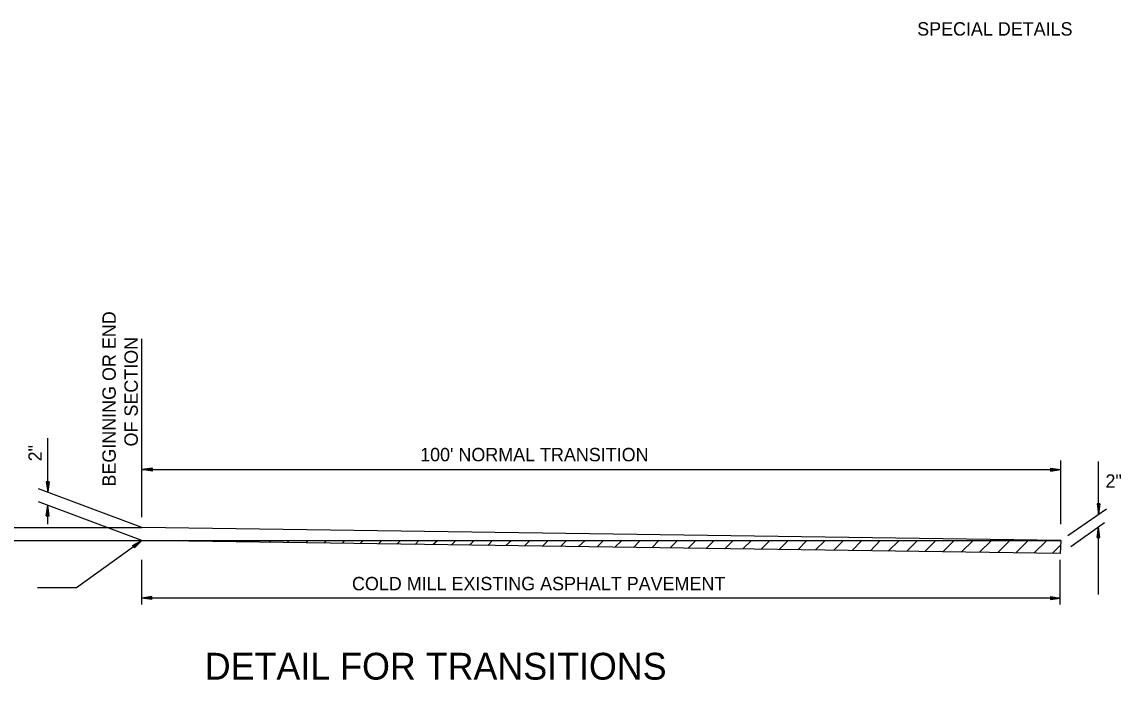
# Model space of a CAD drawing. Extents: x 1955771 to 1955918, y 566326 to 566544.
# Drawn here: x 1955863.97 to 1955913.2, y 566514.53 to 566543.99 of the extents above; entities that cross this region are included whole.
import ezdxf

# ---------------------------------------------------------------- set-up
doc = ezdxf.new("R2010")
doc.units = 0
doc.layers.add('Default', color=7, linetype='Continuous')
doc.layers.add('STAMP', color=7, linetype='Continuous')

msp = doc.modelspace()

# ---------------------------------------------------------------- linework, layer by layer
at = {"layer": 'Default'}
for p, q in [((1955869.343, 566521.819), (1955869.343, 566529.806)), ((1955865.124, 566522.953), (1955865.124, 566525.353)), ((1955910.499, 566521.51), (1955910.499, 566524.352)), ((1955912.186, 566521.953), (1955912.186, 566524.307)), ((1955869.81, 566524.019), (1955869.343, 566523.953)), ((1955869.343, 566523.953), (1955910.499, 566523.953)), ((1955869.81, 566523.886), (1955869.343, 566523.953)), ((1955869.81, 566523.997), (1955869.411, 566523.953)), ((1955869.81, 566523.886), (1955869.411, 566523.953)), ((1955869.81, 566523.997), (1955869.5, 566523.953)), ((1955869.81, 566523.908), (1955869.5, 566523.953)), ((1955869.81, 566523.975), (1955869.589, 566523.953)), ((1955869.81, 566523.908), (1955869.589, 566523.953)), ((1955869.81, 566523.975), (1955869.655, 566523.953)), ((1955869.81, 566523.931), (1955869.655, 566523.953)), ((1955869.81, 566523.953), (1955869.744, 566523.953)), ((1955869.81, 566523.931), (1955869.744, 566523.953)), ((1955869.81, 566523.886), (1955869.81, 566524.019)), ((1955910.032, 566524.019), (1955910.499, 566523.953)), ((1955910.032, 566524.019), (1955910.032, 566523.886)), ((1955910.032, 566523.997), (1955910.344, 566523.953)), ((1955910.032, 566523.997), (1955910.409, 566523.953)), ((1955910.032, 566523.975), (1955910.187, 566523.953)), ((1955910.032, 566523.975), (1955910.255, 566523.953)), ((1955910.032, 566523.886), (1955910.499, 566523.953)), ((1955910.032, 566523.931), (1955910.187, 566523.953)), ((1955910.032, 566523.908), (1955910.344, 566523.953)), ((1955910.032, 566523.886), (1955910.409, 566523.953)), ((1955910.032, 566523.908), (1955910.255, 566523.953)), ((1955910.032, 566523.931), (1955910.099, 566523.953)), ((1955910.032, 566523.953), (1955910.099, 566523.953)), ((1955865.057, 566523.398), (1955865.124, 566522.953)), ((1955865.057, 566523.398), (1955865.124, 566523.02)), ((1955865.19, 566523.398), (1955865.057, 566523.398)), ((1955865.08, 566523.398), (1955865.124, 566523.109)), ((1955865.08, 566523.398), (1955865.124, 566523.175)), ((1955865.102, 566523.398), (1955865.124, 566523.264)), ((1955865.102, 566523.398), (1955865.124, 566523.33)), ((1955865.19, 566523.398), (1955865.124, 566522.953)), ((1955865.146, 566523.398), (1955865.124, 566523.264)), ((1955865.169, 566523.398), (1955865.124, 566523.109)), ((1955865.169, 566523.398), (1955865.124, 566523.02)), ((1955865.146, 566523.398), (1955865.124, 566523.175)), ((1955865.124, 566523.398), (1955865.124, 566523.33)), ((1955869.343, 566521.354), (1955864.702, 566523.087)), ((1955869.343, 566520.777), (1955864.702, 566522.509)), ((1955865.057, 566521.887), (1955865.124, 566522.353)), ((1955865.057, 566521.887), (1955865.124, 566522.287)), ((1955865.08, 566521.887), (1955865.124, 566522.198)), ((1955865.19, 566521.887), (1955865.124, 566522.353)), ((1955865.124, 566521.51), (1955865.124, 566522.353)), ((1955865.169, 566521.887), (1955865.124, 566522.287)), ((1955865.169, 566521.887), (1955865.124, 566522.198)), ((1955910.81, 566520.999), (1955912.541, 566522.198)), ((1955912.12, 566522.419), (1955912.186, 566521.953)), ((1955912.253, 566522.419), (1955912.12, 566522.419)), ((1955912.143, 566522.419), (1955912.186, 566522.109)), ((1955912.143, 566522.419), (1955912.186, 566522.043)), ((1955912.163, 566522.419), (1955912.186, 566522.265)), ((1955912.163, 566522.419), (1955912.186, 566522.198)), ((1955912.253, 566522.419), (1955912.186, 566521.953)), ((1955912.208, 566522.419), (1955912.186, 566522.265)), ((1955912.231, 566522.419), (1955912.186, 566522.109)), ((1955912.253, 566522.419), (1955912.186, 566522.043)), ((1955912.231, 566522.419), (1955912.186, 566522.198)), ((1955912.186, 566522.419), (1955912.186, 566522.353)), ((1955912.208, 566522.419), (1955912.186, 566522.353)), ((1955865.057, 566521.887), (1955865.19, 566521.887)), ((1955865.08, 566521.887), (1955865.124, 566522.132)), ((1955865.102, 566521.887), (1955865.124, 566522.043)), ((1955865.102, 566521.887), (1955865.124, 566521.953)), ((1955865.146, 566521.887), (1955865.124, 566522.132)), ((1955865.146, 566521.887), (1955865.124, 566522.043)), ((1955865.124, 566521.887), (1955865.124, 566521.953)), ((1955857.796, 566521.353), (1955869.343, 566521.353)), ((1955910.499, 566520.777), (1955869.343, 566521.354)), ((1955910.942, 566520.51), (1955912.453, 566521.576)), ((1955912.12, 566520.91), (1955912.186, 566521.377)), ((1955912.143, 566520.91), (1955912.186, 566521.31)), ((1955912.143, 566520.91), (1955912.186, 566521.22)), ((1955912.186, 566518.356), (1955912.186, 566521.377)), ((1955912.253, 566520.91), (1955912.186, 566521.377)), ((1955912.253, 566520.91), (1955912.186, 566521.31)), ((1955912.231, 566520.91), (1955912.186, 566521.22)), ((1955857.796, 566520.776), (1955910.499, 566520.776)), ((1955866.413, 566518.667), (1955869.343, 566520.777)), ((1955868.922, 566520.554), (1955869.343, 566520.777)), ((1955868.945, 566520.554), (1955869.277, 566520.732)), ((1955869.01, 566520.443), (1955869.343, 566520.777)), ((1955869.01, 566520.465), (1955869.277, 566520.732)), ((1955910.476, 566520.198), (1955869.343, 566520.777)), ((1955870.964, 566520.754), (1955870.987, 566520.777)), ((1955871.775, 566520.743), (1955871.808, 566520.777)), ((1955872.586, 566520.731), (1955872.652, 566520.777)), ((1955873.417, 566520.72), (1955873.475, 566520.777)), ((1955874.229, 566520.708), (1955874.296, 566520.777)), ((1955875.039, 566520.697), (1955875.118, 566520.777)), ((1955875.85, 566520.686), (1955875.94, 566520.777)), ((1955876.68, 566520.674), (1955876.784, 566520.777)), ((1955877.491, 566520.663), (1955877.606, 566520.777)), ((1955878.323, 566520.65), (1955878.428, 566520.777)), ((1955879.113, 566520.64), (1955879.25, 566520.777)), ((1955879.945, 566520.628), (1955880.093, 566520.777)), ((1955880.755, 566520.616), (1955880.916, 566520.777)), ((1955881.586, 566520.605), (1955881.738, 566520.777)), ((1955882.374, 566520.594), (1955882.581, 566520.777)), ((1955883.209, 566520.582), (1955883.403, 566520.777)), ((1955884.019, 566520.571), (1955884.225, 566520.777)), ((1955884.83, 566520.558), (1955885.048, 566520.776)), ((1955885.64, 566520.547), (1955885.89, 566520.777)), ((1955886.472, 566520.536), (1955886.712, 566520.777)), ((1955887.282, 566520.524), (1955887.533, 566520.777)), ((1955888.092, 566520.513), (1955888.355, 566520.777)), ((1955888.902, 566520.502), (1955889.198, 566520.777)), ((1955889.735, 566520.49), (1955890.021, 566520.777)), ((1955890.522, 566520.479), (1955890.842, 566520.777)), ((1955891.356, 566520.467), (1955891.665, 566520.777)), ((1955892.188, 566520.456), (1955892.487, 566520.777)), ((1955892.998, 566520.444), (1955893.33, 566520.777)), ((1955893.809, 566520.433), (1955894.152, 566520.777)), ((1955894.62, 566520.422), (1955894.974, 566520.777)), ((1955895.453, 566520.41), (1955895.818, 566520.777)), ((1955896.263, 566520.399), (1955896.64, 566520.777)), ((1955897.073, 566520.387), (1955897.462, 566520.777)), ((1955897.882, 566520.375), (1955898.282, 566520.777)), ((1955898.715, 566520.364), (1955899.127, 566520.777)), ((1955899.504, 566520.353), (1955899.949, 566520.777)), ((1955900.336, 566520.342), (1955900.771, 566520.777)), ((1955901.147, 566520.33), (1955901.592, 566520.777)), ((1955901.978, 566520.318), (1955902.415, 566520.777)), ((1955902.766, 566520.306), (1955903.258, 566520.777)), ((1955903.598, 566520.295), (1955904.08, 566520.777)), ((1955904.414, 566520.288), (1955904.902, 566520.777)), ((1955905.22, 566520.273), (1955905.723, 566520.777)), ((1955906.03, 566520.261), (1955906.567, 566520.777)), ((1955906.862, 566520.249), (1955907.389, 566520.777)), ((1955907.673, 566520.238), (1955908.212, 566520.777)), ((1955908.484, 566520.226), (1955909.032, 566520.777)), ((1955909.293, 566520.215), (1955909.877, 566520.777)), ((1955910.499, 566520.777), (1955910.476, 566520.198)), ((1955912.12, 566520.91), (1955912.253, 566520.91)), ((1955912.163, 566520.91), (1955912.186, 566521.154)), ((1955912.163, 566520.91), (1955912.186, 566521.064)), ((1955912.231, 566520.91), (1955912.186, 566521.154)), ((1955912.208, 566520.91), (1955912.186, 566521.064)), ((1955912.208, 566520.91), (1955912.186, 566520.999)), ((1955912.186, 566520.91), (1955912.186, 566520.999)), ((1955868.922, 566520.554), (1955869.01, 566520.443)), ((1955868.945, 566520.554), (1955869.211, 566520.687)), ((1955868.945, 566520.532), (1955869.143, 566520.643)), ((1955868.945, 566520.532), (1955869.1, 566520.599)), ((1955868.967, 566520.51), (1955869.033, 566520.554)), ((1955868.967, 566520.51), (1955869.033, 566520.554)), ((1955868.988, 566520.465), (1955869.211, 566520.687)), ((1955868.988, 566520.488), (1955869.143, 566520.643)), ((1955868.988, 566520.488), (1955869.1, 566520.599)), ((1955910.125, 566520.203), (1955910.49, 566520.568)), ((1955869.343, 566517.911), (1955869.343, 566519.91)), ((1955910.476, 566517.911), (1955910.476, 566519.91)), ((1955864.658, 566518.667), (1955866.413, 566518.667)), ((1955869.789, 566518.266), (1955869.343, 566518.201)), ((1955869.789, 566518.266), (1955869.343, 566518.201)), ((1955869.789, 566518.266), (1955869.411, 566518.201)), ((1955869.789, 566518.266), (1955869.411, 566518.201)), ((1955869.789, 566518.246), (1955869.5, 566518.201)), ((1955869.789, 566518.246), (1955869.5, 566518.201)), ((1955869.789, 566518.246), (1955869.566, 566518.201)), ((1955869.789, 566518.246), (1955869.566, 566518.201)), ((1955869.789, 566518.133), (1955869.789, 566518.266)), ((1955869.789, 566518.133), (1955869.789, 566518.266)), ((1955910.032, 566518.266), (1955910.476, 566518.201)), ((1955910.032, 566518.266), (1955910.409, 566518.201)), ((1955910.032, 566518.266), (1955910.032, 566518.133)), ((1955910.032, 566518.246), (1955910.321, 566518.201)), ((1955910.032, 566518.246), (1955910.255, 566518.201)), ((1955910.476, 566518.201), (1955869.343, 566518.201)), ((1955869.789, 566518.133), (1955869.343, 566518.201)), ((1955869.789, 566518.133), (1955869.343, 566518.201)), ((1955869.789, 566518.156), (1955869.411, 566518.201)), ((1955869.789, 566518.156), (1955869.411, 566518.201)), ((1955869.789, 566518.156), (1955869.5, 566518.201)), ((1955869.789, 566518.156), (1955869.5, 566518.201)), ((1955869.789, 566518.178), (1955869.566, 566518.201)), ((1955869.789, 566518.178), (1955869.566, 566518.201)), ((1955869.789, 566518.221), (1955869.655, 566518.201)), ((1955869.789, 566518.221), (1955869.655, 566518.201)), ((1955869.789, 566518.178), (1955869.655, 566518.201)), ((1955869.789, 566518.178), (1955869.655, 566518.201)), ((1955869.789, 566518.221), (1955869.722, 566518.201)), ((1955869.789, 566518.221), (1955869.722, 566518.201)), ((1955869.789, 566518.201), (1955869.722, 566518.201)), ((1955869.789, 566518.201), (1955869.722, 566518.201)), ((1955910.032, 566518.221), (1955910.166, 566518.201)), ((1955910.032, 566518.221), (1955910.099, 566518.201)), ((1955910.032, 566518.133), (1955910.476, 566518.201)), ((1955910.032, 566518.178), (1955910.166, 566518.201)), ((1955910.032, 566518.156), (1955910.321, 566518.201)), ((1955910.032, 566518.156), (1955910.409, 566518.201)), ((1955910.032, 566518.178), (1955910.255, 566518.201)), ((1955910.032, 566518.201), (1955910.099, 566518.201))]:
    msp.add_line(p, q, dxfattribs=at)

# ---------------------------------------------------------------- texts
for s, p in [('BEGINNING OR END', (1955868.17, 566523.192)), ('OF SECTION', (1955869.156, 566524.987)), ('2"', (1955864.858, 566524.319))]:
    msp.add_text(s, height=0.6, rotation=90, dxfattribs=at).set_placement(p)
for s, height, p in [("100' NORMAL TRANSITION", 0.6, (1955881.803, 566524.322)), ('2"', 0.6, (1955912.499, 566523.136)), ('COLD MILL EXISTING ASPHALT PAVEMENT', 0.6, (1955878.75, 566518.547)), ('DETAIL FOR TRANSITIONS', 1.2, (1955872.157, 566514.549))]:
    msp.add_text(s, height=height, dxfattribs=at).set_placement(p)
at = {"layer": 'STAMP'}
msp.add_text('SPECIAL DETAILS', height=0.6, rotation=360, dxfattribs=at).set_placement((1955904.066, 566543.379))

doc.saveas('drawing.dxf')
